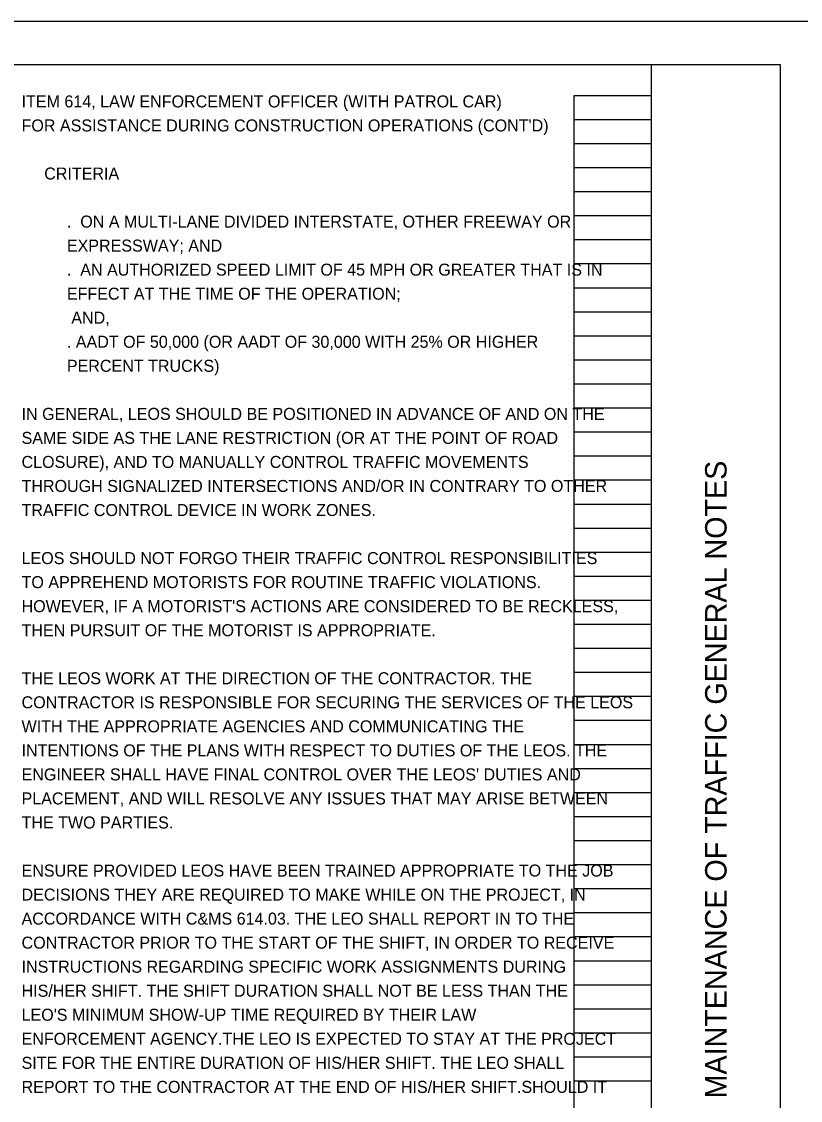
# Model space of a CAD drawing. Extents: x -18.5 to 46, y -14.2 to 42.5.
# Drawn here: x 24.66 to 33.74, y 9.43 to 22 of the extents above; entities that cross this region are included whole.
import ezdxf

# ---------------------------------------------------------------- set-up
doc = ezdxf.new("R2010")
doc.units = 0
for name, color, linetype in [('SH_Border', 7, 'Continuous'), ('SH_Cut_Line', 7, 'Continuous'), ('SH_Data', 7, 'Continuous'), ('SH_Text', 7, 'Continuous')]:
    doc.layers.add(name, color=color, linetype=linetype)

msp = doc.modelspace()

# ---------------------------------------------------------------- linework, layer by layer
at = {"layer": 'SH_Border'}
msp.add_line((32, 0.5), (32, 21.5), dxfattribs=at)
msp.add_lwpolyline([(1.5, 21.5), (33.5, 21.5), (33.5, 0.5), (1.5, 0.5)], close=True, dxfattribs=at)
at = {"layer": 'SH_Cut_Line'}
msp.add_lwpolyline([(0, 0), (34, 0), (34, 22), (0, 22)], close=True, dxfattribs=at)
at = {"layer": 'SH_Data'}
for p, q in [((31.1, 0.98), (31.1, 21.14)), ((31.1, 21.14), (32, 21.14)), ((32, 0.98), (32, 21.14)), ((31.1, 20.86), (32, 20.86)), ((31.1, 20.58), (32, 20.58)), ((31.1, 20.3), (32, 20.3)), ((31.1, 20.02), (32, 20.02)), ((31.1, 19.74), (32, 19.74)), ((31.1, 19.46), (32, 19.46)), ((31.1, 19.18), (32, 19.18)), ((31.1, 18.9), (32, 18.9)), ((31.1, 18.62), (32, 18.62)), ((31.1, 18.34), (32, 18.34)), ((31.1, 18.06), (32, 18.06)), ((31.1, 17.78), (32, 17.78)), ((31.1, 17.5), (32, 17.5)), ((31.1, 17.22), (32, 17.22)), ((31.1, 16.94), (32, 16.94)), ((31.1, 16.66), (32, 16.66)), ((31.1, 16.38), (32, 16.38)), ((31.1, 16.1), (32, 16.1)), ((31.1, 15.82), (32, 15.82)), ((31.1, 15.54), (32, 15.54)), ((31.1, 15.26), (32, 15.26)), ((31.1, 14.98), (32, 14.98)), ((31.1, 14.7), (32, 14.7)), ((31.1, 14.42), (32, 14.42)), ((31.1, 14.14), (32, 14.14)), ((31.1, 13.86), (32, 13.86)), ((31.1, 13.58), (32, 13.58)), ((31.1, 13.3), (32, 13.3)), ((31.1, 13.02), (32, 13.02)), ((31.1, 12.74), (32, 12.74)), ((31.1, 12.46), (32, 12.46)), ((31.1, 12.18), (32, 12.18)), ((31.1, 11.9), (32, 11.9)), ((31.1, 11.62), (32, 11.62)), ((31.1, 11.34), (32, 11.34)), ((31.1, 11.06), (32, 11.06)), ((31.1, 10.78), (32, 10.78)), ((31.1, 10.5), (32, 10.5)), ((31.1, 10.22), (32, 10.22)), ((31.1, 9.94), (32, 9.94)), ((31.1, 9.66), (32, 9.66))]:
    msp.add_line(p, q, dxfattribs=at)

# ---------------------------------------------------------------- texts
msp.add_text('MAINTENANCE OF TRAFFIC GENERAL NOTES', height=0.25, rotation=90, dxfattribs=at).set_placement((32.875, 9.455))
at = {"layer": 'SH_Text'}
for s, p in [('ITEM 614, LAW ENFORCEMENT OFFICER (WITH PATROL CAR)', (24.66, 21)), ("FOR ASSISTANCE DURING CONSTRUCTION OPERATIONS (CONT'D)", (24.66, 20.72)), ('CRITERIA', (24.924, 20.16)), ('.  ON A MULTI-LANE DIVIDED INTERSTATE, OTHER FREEWAY OR ', (25.188, 19.6)), ('EXPRESSWAY; AND', (25.188, 19.32)), ('.  AN AUTHORIZED SPEED LIMIT OF 45 MPH OR GREATER THAT IS IN ', (25.188, 19.04)), ('EFFECT AT THE TIME OF THE OPERATION;', (25.188, 18.76)), (' AND,', (25.188, 18.48)), ('. AADT OF 50,000 (OR AADT OF 30,000 WITH 25% OR HIGHER ', (25.188, 18.2)), ('PERCENT TRUCKS)', (25.188, 17.92)), ('IN GENERAL, LEOS SHOULD BE POSITIONED IN ADVANCE OF AND ON THE ', (24.66, 17.36)), ('SAME SIDE AS THE LANE RESTRICTION (OR AT THE POINT OF ROAD ', (24.66, 17.08)), ('CLOSURE), AND TO MANUALLY CONTROL TRAFFIC MOVEMENTS ', (24.66, 16.8)), ('THROUGH SIGNALIZED INTERSECTIONS AND/OR IN CONTRARY TO OTHER ', (24.66, 16.52)), ('TRAFFIC CONTROL DEVICE IN WORK ZONES.', (24.66, 16.24)), ('LEOS SHOULD NOT FORGO THEIR TRAFFIC CONTROL RESPONSIBILITIES ', (24.66, 15.68)), ('TO APPREHEND MOTORISTS FOR ROUTINE TRAFFIC VIOLATIONS. ', (24.66, 15.4)), ("HOWEVER, IF A MOTORIST'S ACTIONS ARE CONSIDERED TO BE RECKLESS, ", (24.66, 15.12)), ('THEN PURSUIT OF THE MOTORIST IS APPROPRIATE.', (24.66, 14.84)), ('THE LEOS WORK AT THE DIRECTION OF THE CONTRACTOR. THE ', (24.66, 14.28)), ('CONTRACTOR IS RESPONSIBLE FOR SECURING THE SERVICES OF THE LEOS ', (24.66, 14)), ('WITH THE APPROPRIATE AGENCIES AND COMMUNICATING THE ', (24.66, 13.72)), ('INTENTIONS OF THE PLANS WITH RESPECT TO DUTIES OF THE LEOS. THE ', (24.66, 13.44)), ("ENGINEER SHALL HAVE FINAL CONTROL OVER THE LEOS' DUTIES AND ", (24.66, 13.16)), ('PLACEMENT, AND WILL RESOLVE ANY ISSUES THAT MAY ARISE BETWEEN ', (24.66, 12.88)), ('THE TWO PARTIES.', (24.66, 12.6)), ('ENSURE PROVIDED LEOS HAVE BEEN TRAINED APPROPRIATE TO THE JOB ', (24.66, 12.04)), ('DECISIONS THEY ARE REQUIRED TO MAKE WHILE ON THE PROJECT, IN ', (24.66, 11.76)), ('ACCORDANCE WITH C&MS 614.03. THE LEO SHALL REPORT IN TO THE ', (24.66, 11.48)), ('CONTRACTOR PRIOR TO THE START OF THE SHIFT, IN ORDER TO RECEIVE ', (24.66, 11.2)), ('INSTRUCTIONS REGARDING SPECIFIC WORK ASSIGNMENTS DURING ', (24.66, 10.92)), ('HIS/HER SHIFT. THE SHIFT DURATION SHALL NOT BE LESS THAN THE ', (24.66, 10.64)), ("LEO'S MINIMUM SHOW-UP TIME REQUIRED BY THEIR LAW ", (24.66, 10.36)), ('ENFORCEMENT AGENCY.THE LEO IS EXPECTED TO STAY AT THE PROJECT ', (24.66, 10.08)), ('SITE FOR THE ENTIRE DURATION OF HIS/HER SHIFT. THE LEO SHALL ', (24.66, 9.8)), ('REPORT TO THE CONTRACTOR AT THE END OF HIS/HER SHIFT.SHOULD IT ', (24.66, 9.52))]:
    msp.add_text(s, height=0.14, dxfattribs=at).set_placement(p)

doc.saveas('drawing.dxf')
